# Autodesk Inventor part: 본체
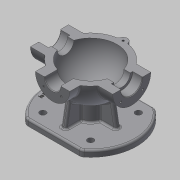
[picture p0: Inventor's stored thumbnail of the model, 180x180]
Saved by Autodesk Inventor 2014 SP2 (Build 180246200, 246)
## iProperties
Created: 2015-12
Part Number: 본체
Material: 일반
Document SubType Name: Modeling
Designer: mduedu
Density: 1 g/cm^3
Appearance: 기본값
Author: mduedu
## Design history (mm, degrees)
sketch "스케치1"
  geometry: L1 (-53, 0)-(53, 0); A1 r 53 centre (0, 0) between (53, 0) and (-53, 0); 2 further points
  constraints: 2 coincident, 2 end point, 2 point on circle, 1 centre point, 1 horizontal, 1 midpoint
  dimensions: "d0" = 53 radius of A1
revolve "회전1" sketch "스케치1" stored, may be unused: angle "d2" = 90 deg
feature "쉘1" dims "d11" = 10
node "작업 평면1"
sketch "스케치2"
  geometry: C1 r 31 at (0, 0); 1 further point
  constraints: 1 centre point, 1 coincident
  dimensions: "d4" = 62 diameter of C1
extrude "돌출1" join sketch "스케치2" stored distance "d5" = 10; taper "d6" = 0 deg
node "작업 평면2"
sketch "스케치3"
  geometry: C1 r 28 at (0, 0); 1 further point
  constraints: 1 centre point, 1 coincident
  dimensions: "d8" = 56 diameter of C1
extrude "돌출2" join sketch "스케치3" stored distance "d9" = 10; taper "d10" = 0 deg
hole "구멍1" diameter "d14" = 35; stored, may be unused: countersink angle "d18" = 90 deg, drill point angle "d20" = 0 deg; dims "d12" = 10, "d13" = 10, "d15" = 6, "d16" = 4, "d17" = 2, "d19" = 16
hole "구멍2" diameter "d23" = 27; stored, may be unused: countersink angle "d27" = 90 deg, drill point angle "d29" = 0 deg; dims "d21" = 10, "d22" = 10, "d24" = 6, "d25" = 4, "d26" = 2, "d28" = 16
fillet "모깎기1" dims "d30" = 0.3
hole "구멍3" diameter "d33" = 26; stored, may be unused: countersink angle "d37" = 90 deg, drill point angle "d39" = 0 deg; dims "d31" = 10, "d32" = 10, "d34" = 6, "d35" = 4, "d36" = 2, "d38" = 16
chamfer "모따기1" distance "d40" = 1; stored, may be unused: second distance "d41" = 2, angle "d42" = 45 deg
sketch "스케치4"
  geometry: L1 (0, 0)-(0, -25); L2 (0, 0)-(-17.678, -17.678); A1 r 25 centre (0, 0) between (-17.678, -17.678) and (0, -25); 1 further point
  constraints: 4 end point, 2 point on circle, 1 centre point, 1 coincident, 1 vertical
  dimensions: "d43" = 50 diameter of A1; "d47" = 45 deg angle of L1 L2
hole "구멍4" sketch "스케치4" at (-17.678, -17.678) diameter "d49" = 3.242; stored, may be unused: countersink angle "d53" = 90 deg, drill point angle "d55" = 118 deg; dims "d50" = 11, "d51" = 4, "d52" = 2, "d54" = 13
sketch "스케치5"
  geometry: L1 (0, 0)-(0, -20); L2 (0, 0)-(-14.142, -14.142); A1 r 20 centre (0, 0) between (0, -20) and (-14.142, -14.142); 2 further points
  constraints: 4 end point, 2 coincident, 2 point on circle, 1 centre point, 1 vertical
  dimensions: "d59" = 40 diameter of A1; "d65" = 45 deg angle of L1 L2
hole "구멍5" sketch "스케치5" at (-14.142, -14.142) diameter "d67" = 3.242; stored, may be unused: countersink angle "d71" = 90 deg, drill point angle "d73" = 118 deg; dims "d68" = 8, "d69" = 4, "d70" = 2, "d72" = 10
node "작업 평면3"
sketch "스케치6"
  geometry: C1 r 75 at (0, 0); 1 further point
  constraints: 1 centre point, 1 coincident
  dimensions: "d78" = 150 diameter of C1
extrude "돌출3" join sketch "스케치6" distance "d80" = 10; taper "d81" = 0 deg
sketch "스케치7"
  geometry: C1 r 20 at (0, 0); 1 further point
  constraints: 1 centre point, 1 coincident
  dimensions: "d82" = 40 diameter of C1
extrude "돌출4" join sketch "스케치7" stored distance "d84" = 10; taper "d85" = 0 deg
sketch "스케치8"
  geometry: 2 further points
  constraints: 1 coincident
hole "구멍6" sketch "스케치8" at (0, 0) diameter "d86" = 20; stored, may be unused: countersink angle "d90" = 90 deg, drill point angle "d92" = 118 deg; dims "d87" = 7, "d88" = 40, "d89" = 5, "d91" = 10
fillet "모깎기2" dims "d93" = 0.3
sketch "스케치9"
  geometry: L1 (75, -75)-(-75, -75) reference; L2 (-45, -75)-(-38.245, -36.692); A1 r 53 centre (0, 0) between (42.988, 31) and (42.988, -31) reference; 1 further point
  constraints: 2 end point, 1 point on circle, 1 point on line
  dimensions: "d94" = 45 horizontal distance of L2.start point (0, 0); "d95" = 80 deg angle of L2 L1
feature "리브1" sketch "스케치9" dims "d96" = 1, "d97" = 8, "d98" = 0, "d99" = 0, "d100" = 1, "d101" = 1
sketch "스케치14"
  geometry: L1 (-45, 110)-(45, 110); L2 (45, 110)-(45, 60); L3 (45, 60)-(-45, 60); L4 (-45, 60)-(-45, 110); L5 (-45, 110)-(45, 60); L6 (45, 110)-(-45, 60); L7 (-75, 0)-(75, 0); L8 (-45, -110)-(45, -110); L9 (45, -110)-(45, -60); L10 (45, -60)-(-45, -60); L11 (-45, -60)-(-45, -110); L12 (-45, -110)-(45, -60); L13 (45, -110)-(-45, -60); A1 r 75 centre (0, 0) between (45, 60) and (-45, 60) reference; 4 further points
  constraints: 26 end point, 5 midpoint, 5 symmetric about line, 4 point on circle, 2 parallel, 2 perpendicular, 1 coincident, 1 horizontal
  dimensions: "d151" = 15 distance edge to line of A1 L3; "d152" = 50 distance of L3.end L1.start
extrude "돌출7" cut sketch "스케치14" stored distance "d153" = 0; taper "d154" = 0 deg
fillet "모깎기9" dims "d155" = 10
sketch "스케치10"
  geometry: L1 (0, 0)-(0, -55); L2 (0, 0)-(-38.891, -38.891); A1 r 55 centre (0, 0) between (0, -55) and (-38.891, -38.891); 2 further points
  constraints: 4 end point, 2 coincident, 2 point on circle, 1 centre point, 1 vertical
  dimensions: "d105" = 110 diameter of A1; "d107" = 45 deg angle of L1 L2
hole "구멍7" sketch "스케치10" at (-38.891, -38.891) diameter "d109" = 10; stored, may be unused: countersink angle "d113" = 90 deg, drill point angle "d115" = 118 deg; dims "d110" = 7, "d111" = 40, "d112" = 5, "d114" = 10
fillet "모깎기3" dims "d120" = 3
fillet "모깎기4" dims "d121" = 3, "d122" = 3
fillet "모깎기5" dims "d123" = 3
fillet "모깎기6" dims "d124" = 3
sketch "스케치11"
  geometry: 2 further points
  constraints: 1 vertical alignment, 1 other
  dimensions: "d157" = 63 distance of point (0, 63) point (0, 0)
feature "엠보싱1" sketch "스케치11" dims "d125" = 0.5, "d126" = 0
sketch "스케치12"
  geometry: L1 (0, 100)-(0, -100); L2 (0, 100)-(100, 100); L3 (100, 100)-(100, -100); L4 (100, -100)-(0, -100); 2 further points
  constraints: 8 end point, 3 perpendicular, 1 coincident, 1 midpoint, 1 vertical
  dimensions: "d127" = 200 distance of L2.end L3.end; "d129" = 100 distance between parallel lines of L1 L3
extrude "돌출5" cut sketch "스케치12" stored distance "d130" = 10; taper "d131" = 0 deg
sketch "스케치13"
  geometry: C1 r 7 at (0, 53); A1 r 53 centre (0, 0) between (42.113, 32.179) and (-42.113, 32.179) reference; 1 further point
  constraints: 1 centre point, 1 point on circle
  dimensions: "d132" = 14 diameter of C1
extrude "돌출6" join sketch "스케치13" distance "d134" = 15; taper "d135" = 0 deg; dims "d29" = 0
hole "구멍8" diameter "d139" = 3.242; stored, may be unused: countersink angle "d143" = 90 deg, drill point angle "d145" = 118 deg; dims "d140" = 8, "d141" = 4, "d142" = 2, "d144" = 10, "d148" = 10, "d149" = 10
fillet "모깎기7" dims "d146" = 3
fillet "모깎기8" dims "d147" = 3
node "솔리드1"
mirror "대칭1"
mirror "대칭2"
pattern_circular "원형 패턴1" dims angle "d57" = 360 deg
mirror "대칭3"
pattern_circular "원형 패턴2" dims angle "d75" = 360 deg
pattern_circular "원형 패턴3" dims angle "d103" = 360 deg
pattern_circular "원형 패턴4" dims angle "d118" = 360 deg
other parameters: "d3" = 67, "d7" = 62, "d77" = -85
